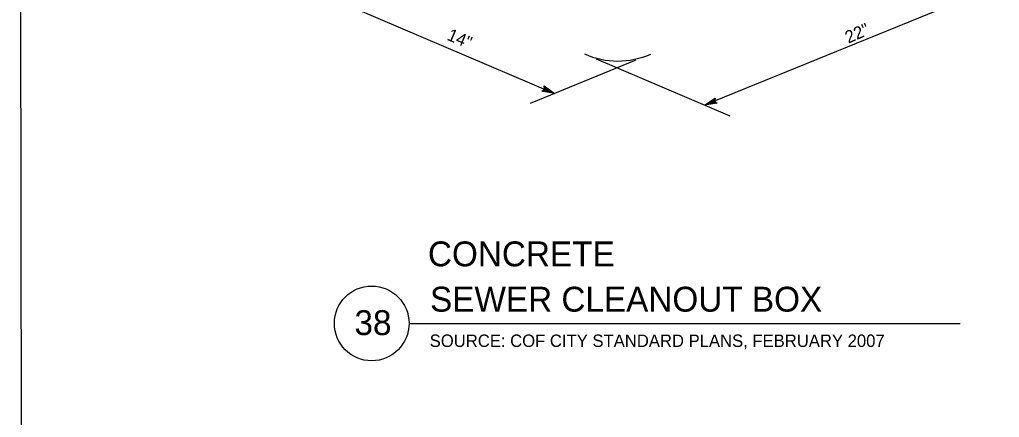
# Model space of a CAD drawing. Extents: x -121933 to -117742, y -103160 to -100084.
# Drawn here: x -121211 to -120738.6, y -101681.4 to -101489.7 of the extents above; entities that cross this region are included whole.
import ezdxf

# ---------------------------------------------------------------- set-up
doc = ezdxf.new("R2010")
doc.units = 0
for name, color, linetype in [('G-MARK', 7, 'Continuous'), ('G-TEXT', 7, 'Continuous'), ('Misc CnstDet(22)', 7, 'Continuous')]:
    doc.layers.add(name, color=color, linetype=linetype)

msp = doc.modelspace()

# ---------------------------------------------------------------- linework, layer by layer
at = {"layer": 'G-MARK'}
for p, q in [((-120729.29, -101469.09), (-120880.79, -101531.02)), ((-121059.07, -101480.05), (-120953.15, -101525.32)), ((-120913.99, -101509.32), (-120964.88, -101530.12)), ((-120868.44, -101536.3), (-120932.91, -101508.74))]:
    msp.add_line(p, q, dxfattribs=at)
at = {"layer": 'G-TEXT'}
for p, q in [((-120959.18, -101524.14), (-120957.91, -101523.24)), ((-120953.15, -101525.32), (-120959.18, -101524.14)), ((-120959.18, -101524.14), (-120959.18, -101524.14)), ((-120954.42, -101524.77), (-120958.82, -101523.91)), ((-120955.68, -101524.22), (-120958.52, -101523.66)), ((-120956.95, -101523.66), (-120958.16, -101523.43)), ((-120957.91, -101523.24), (-120958.11, -101521.7)), ((-120958.11, -101521.7), (-120958.11, -101521.7)), ((-120958.11, -101521.7), (-120953.15, -101525.32)), ((-120958.06, -101522.11), (-120954.41, -101524.77)), ((-120957.98, -101522.53), (-120955.68, -101524.22)), ((-120957.96, -101522.92), (-120956.95, -101523.66)), ((-120953.15, -101525.32), (-120953.15, -101525.32)), ((-120880.79, -101531.02), (-120875.7, -101527.58)), ((-120879.5, -101530.51), (-120875.79, -101528)), ((-120878.22, -101530.01), (-120875.83, -101528.39)), ((-120876.94, -101529.5), (-120875.91, -101528.81)), ((-120875.7, -101527.58), (-120875.96, -101529.11)), ((-120875.7, -101527.58), (-120875.7, -101527.58)), ((-120874.72, -101530.06), (-120880.79, -101531.02)), ((-120880.79, -101531.02), (-120880.79, -101531.02)), ((-120875.05, -101529.81), (-120879.51, -101530.51)), ((-120875.4, -101529.56), (-120878.22, -101530.01)), ((-120875.69, -101529.3), (-120876.94, -101529.5)), ((-120875.96, -101529.11), (-120874.72, -101530.06)), ((-120874.72, -101530.06), (-120874.72, -101530.06))]:
    msp.add_line(p, q, dxfattribs=at)
at = {"layer": 'Misc CnstDet(22)'}
for p, q in [((-121211.03, -101153.11), (-121209.67, -102136.14)), ((-121023.28, -101636.1), (-120757.53, -101636.1))]:
    msp.add_line(p, q, dxfattribs=at)
msp.add_circle((-121041.28, -101636.1), 18, dxfattribs=at)
msp.add_arc((-120922.62, -101470.3), 39.39, 246.0493, 293.7493, dxfattribs=at)

# ---------------------------------------------------------------- texts
for s, rotation, p in [('14"', 337.0306, (-121005.38, -101499.34)), ('22"', 23.6156, (-120811.48, -101501.37))]:
    msp.add_text(s, height=6, rotation=rotation, dxfattribs=at).set_placement(p)
for s, height, p in [('CONCRETE', 12, (-121014.16, -101608.6)), ('SEWER CLEANOUT BOX', 12, (-121013.12, -101630.43)), ('38', 12, (-121049.59, -101641.73)), ('SOURCE: COF CITY STANDARD PLANS, FEBRUARY 2007', 6, (-121013.31, -101647.45))]:
    msp.add_text(s, height=height, dxfattribs=at).set_placement(p)

doc.saveas('drawing.dxf')
